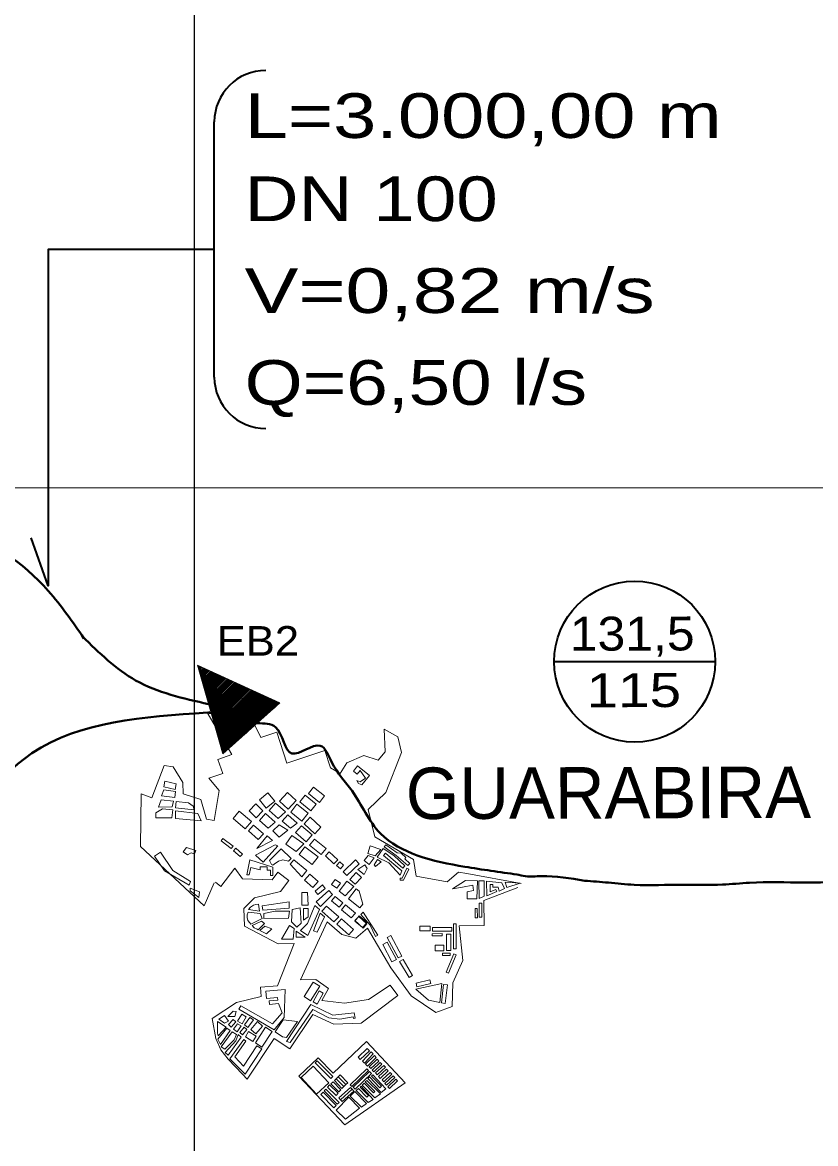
# Model space of a CAD drawing. Extents: x 0 to 1682, y 0 to 1188.
# Drawn here: x 1003.2 to 1062.2, y 569.6 to 652.9 of the extents above; entities that cross this region are included whole.
import ezdxf
from ezdxf.enums import TextEntityAlignment as Align

# ---------------------------------------------------------------- set-up
doc = ezdxf.new("R2010")
doc.units = 0
doc.header["$LTSCALE"] = 1.3
doc.linetypes.add('DOT_DASHED', pattern=[7.7, 5, -1.2, 0.3, -1.2])
doc.linetypes.add('LONG_DASHED', pattern=[7.5, 6, -1.5])
for name, color, linetype, lineweight in [('1', 7, 'DOT_DASHED', 13), ('4', 7, 'Continuous', 13), ('5', 7, 'LONG_DASHED', 25), ('6', 7, 'Continuous', 40), ('63', 7, 'Continuous', 25), ('8', 7, 'Continuous', 35), ('9', 7, 'Continuous', 40)]:
    doc.layers.add(name, color=color, linetype=linetype, lineweight=lineweight)

msp = doc.modelspace()

# ---------------------------------------------------------------- linework, layer by layer
at = {"layer": '1', "linetype": 'Continuous'}
for p, q in [((1026.861, 597.071), (1027.349, 597.865)), ((1016.751, 587.232), (1017.484, 588.935)), ((1019.152, 577.667), (1018.821, 577.878))]:
    msp.add_line(p, q, dxfattribs=at)
for points in [[(1026.861, 597.071), (1026.144, 597.484), (1025.726, 598.765), (1022.895, 597.841), (1022.145, 600.136), (1020.957, 599.748), (1019.155, 603.461), (1018.002, 602.901), (1018.321, 602.244), (1016.97, 601.589), (1018.815, 598.469), (1017.778, 598.113), (1018.135, 597.076), (1017.098, 596.719), (1017.874, 595.814), (1017.505, 593.579), (1016.935, 593.673), (1016.506, 595.124), (1015.18, 595.562), (1015.177, 596.402), (1014.445, 597.572), (1013.782, 597.659), (1012.862, 595.246), (1012.074, 595.547), (1012.011, 591.64), (1016.751, 587.232)], [(1040.301, 588.887), (1040.301, 588.887), (1036.266, 589.629), (1035.645, 589.744), (1034.799, 589.021), (1032.499, 589.43), (1032.307, 590.674), (1029.438, 592.363), (1028.942, 594.399), (1030.257, 595.647), (1031.416, 598.631), (1031.149, 599.8), (1030.13, 600.363), (1030.21, 598.665), (1029.685, 598.06), (1028.628, 598.397), (1027.349, 597.865)], [(1017.585, 588.981), (1017.983, 588.673), (1019.028, 590.023), (1019.594, 589.23), (1021.802, 589.17), (1022.22, 589.724), (1023.039, 589.107), (1022.421, 588.289), (1020.481, 587.818), (1019.688, 587.042), (1019.737, 585.715), (1022.258, 584.418), (1023.429, 584.444), (1022.201, 581.279), (1020.943, 581.186), (1020.993, 580.503), (1019.154, 580.044), (1017.35, 578.862), (1017.613, 577.369), (1017.987, 576.531), (1018.532, 575.853), (1019.591, 574.726), (1019.948, 574.346), (1021.955, 577.379), (1023.127, 576.604), (1024.815, 579.156), (1026.387, 578.433), (1028.411, 578.528), (1031.146, 580.574), (1030.575, 581.337), (1028.966, 580.278), (1027.187, 579.994), (1025.495, 580.2), (1025.993, 581.082), (1025.046, 581.758), (1023.911, 581.744), (1025.901, 586.038), (1026.972, 585.116), (1028.029, 584.83), (1028.884, 585.568), (1030.617, 582.633), (1032.136, 580.554), (1033.962, 579.298), (1035.191, 579.749), (1035.227, 581.513), (1035.963, 583.166), (1035.704, 585.754), (1037.563, 585.774), (1037.544, 587.633), (1040.071, 588.608)], [(1018.821, 577.878), (1018.017, 576.763), (1018.277, 576.575), (1018.981, 577.269), (1019.152, 577.667)]]:
    msp.add_lwpolyline(points, dxfattribs=at)
for points in [[(1029.039, 596.904), (1028.157, 597.622), (1027.843, 597.237), (1028.116, 597.015), (1028.338, 597.288), (1028.733, 596.729), (1028.343, 596.453), (1028.106, 596.54), (1028.214, 596.314), (1028.468, 596.221)], [(1014.608, 595.881), (1013.745, 596.079), (1013.837, 596.483), (1014.681, 596.29)], [(1013.572, 595.403), (1013.745, 595.854), (1014.633, 595.731), (1014.57, 595.274)], [(1021.37, 594.483), (1020.852, 595.105), (1021.474, 595.623), (1021.993, 595.001)], [(1022.997, 594.411), (1022.357, 595.003), (1022.948, 595.643), (1023.588, 595.051)], [(1025.321, 594.92), (1024.498, 595.587), (1024.882, 596.061), (1025.705, 595.394)], [(1014.386, 594.579), (1013.349, 594.576), (1013.547, 595.115), (1014.485, 595.017)], [(1016.012, 594.359), (1014.612, 594.517), (1014.665, 594.986), (1015.593, 594.88), (1015.924, 594.646)], [(1020.612, 593.78), (1020.094, 594.281), (1020.595, 594.799), (1021.113, 594.299)], [(1022.254, 593.724), (1021.584, 594.316), (1022.058, 594.854), (1022.792, 594.206)], [(1024.018, 593.532), (1023.18, 594.199), (1023.641, 594.779), (1024.479, 594.112)], [(1024.669, 594.295), (1023.862, 594.962), (1024.259, 595.443), (1025.067, 594.776)], [(1014.339, 593.766), (1013.164, 593.762), (1013.163, 594.137), (1013.662, 594.452), (1014.425, 594.366)], [(1014.614, 593.716), (1016.539, 593.559), (1016.275, 594.097), (1014.625, 594.279)], [(1019.809, 592.956), (1018.895, 593.73), (1019.353, 594.271), (1020.267, 593.498)], [(1021.511, 593.007), (1020.856, 593.583), (1021.308, 594.097), (1022.038, 593.455)], [(1023.168, 592.997), (1022.559, 593.527), (1022.959, 593.987), (1023.674, 593.365)], [(1020.769, 592.153), (1020.038, 592.805), (1020.423, 593.237), (1021.155, 592.585)], [(1022.319, 592.325), (1021.862, 592.795), (1022.332, 593.252), (1022.971, 592.844)], [(1024.326, 591.996), (1023.534, 592.678), (1023.974, 593.189), (1024.766, 592.507)], [(1024.963, 592.591), (1024.17, 593.319), (1024.623, 593.812), (1025.416, 593.084)], [(1018.895, 591.677), (1018.143, 592.238), (1018.013, 592.063), (1018.765, 591.502)], [(1021.833, 592.095), (1021.437, 592.429), (1020.658, 591.503)], [(1023.599, 591.278), (1022.822, 591.824), (1023.273, 592.466), (1024.166, 591.838)], [(1025.454, 591.041), (1024.586, 591.753), (1024.948, 592.194), (1025.816, 591.482)], [(1015.522, 591.016), (1015.196, 591.253), (1015.433, 591.579), (1016.121, 591.343), (1016.035, 591.092), (1015.784, 591.178)], [(1019.597, 591.078), (1019.095, 591.515), (1018.935, 591.33), (1019.436, 590.894)], [(1022.215, 591.685), (1021.139, 590.48), (1020.556, 591), (1022.017, 591.761)], [(1021.61, 590.603), (1022.474, 591.473), (1023.206, 590.746), (1023.008, 590.546), (1022.598, 590.652), (1022.279, 590.544), (1021.964, 590.339), (1021.843, 590.26), (1021.749, 590.293)], [(1024.787, 590.308), (1023.812, 591.051), (1024.239, 591.611), (1025.214, 590.868)], [(1029.462, 590.946), (1028.905, 591.126), (1029.085, 591.683), (1029.881, 591.425)], [(1031.654, 590.214), (1030.835, 590.973), (1030.05, 591.505), (1029.605, 590.848), (1030.473, 590.438), (1031.305, 589.509), (1031.44, 589.827), (1030.086, 590.982), (1030.217, 591.136), (1031.519, 590.025)], [(1031.881, 590.226), (1031.028, 590.985), (1030.129, 591.607), (1030.244, 591.773), (1031.103, 591.178), (1031.391, 591.145), (1031.732, 590.817), (1031.653, 590.734), (1032.022, 590.379)], [(1015.629, 588.777), (1013.801, 589.835), (1013.072, 590.934), (1013.512, 591.225), (1014.423, 589.851), (1015.74, 589.04)], [(1019.926, 589.533), (1020.135, 590.66), (1021.854, 590.117), (1021.856, 589.478), (1021.674, 589.477), (1021.673, 589.888), (1021.43, 589.887), (1021.429, 590.131), (1020.912, 590.129), (1020.913, 589.901), (1020.228, 590.082), (1020.087, 589.548)], [(1024.378, 589.85), (1023.403, 590.654), (1023.133, 590.326), (1024, 589.378)], [(1026.398, 590.359), (1025.758, 590.95), (1026.032, 591.246), (1026.672, 590.654)], [(1027.343, 589.479), (1027.069, 589.767), (1027.989, 590.643), (1028.263, 590.354)], [(1029.021, 590.297), (1028.645, 590.591), (1028.94, 590.967), (1029.394, 590.798)], [(1029.894, 590.504), (1029.487, 590.162), (1029.381, 590.288), (1029.633, 590.685)], [(1026.871, 589.98), (1026.596, 590.222), (1026.839, 590.497), (1027.113, 590.254)], [(1027.968, 588.842), (1027.587, 589.19), (1028.052, 589.698), (1028.439, 589.343)], [(1028.65, 589.559), (1028.178, 589.923), (1028.679, 590.274), (1028.86, 590.016)], [(1031.567, 589.134), (1031.306, 589.134), (1031.305, 589.281), (1031.453, 589.282), (1031.814, 590.021), (1031.965, 589.948)], [(1024.823, 588.604), (1024.213, 589.15), (1024.604, 589.586), (1025.214, 589.04)], [(1026.601, 588.548), (1026.221, 588.821), (1026.493, 589.202), (1026.874, 588.929)], [(1027.226, 587.987), (1026.784, 588.321), (1027.348, 589.067), (1027.867, 588.675)], [(1037.023, 587.756), (1036.288, 587.754), (1036.286, 588.285), (1036.773, 588.372), (1036.703, 588.763), (1035.957, 588.63), (1035.212, 588.497), (1036.172, 589.123), (1037.07, 589.083)], [(1037.177, 587.79), (1037.552, 587.951), (1037.548, 589.087), (1037.155, 589.086)], [(1038.67, 588.329), (1039.075, 588.528), (1038.877, 588.933), (1037.737, 589.062), (1037.753, 587.972), (1038.499, 588.29), (1038.434, 588.444), (1038.011, 588.264), (1038, 588.826), (1038.209, 588.83), (1038.213, 588.621), (1038.603, 588.629)], [(1039.246, 588.594), (1039.113, 589), (1040.241, 588.912)], [(1016.344, 587.865), (1015.718, 588.339), (1015.717, 588.552), (1016.393, 588.266)], [(1024.491, 587.29), (1024.013, 587.289), (1024.01, 588.224), (1024.433, 588.225)], [(1025.204, 588.073), (1024.991, 588.331), (1025.539, 588.784), (1025.752, 588.526)], [(1025.405, 587.175), (1025.084, 587.524), (1026.006, 588.37), (1026.279, 588.072)], [(1028.323, 587.093), (1027.47, 587.76), (1028.042, 588.491), (1028.266, 588.315), (1028.55, 587.367)], [(1020.87, 586.83), (1020.057, 586.964), (1020.202, 587.123), (1020.415, 587.274), (1020.599, 587.321), (1020.783, 587.369)], [(1023.079, 587.063), (1023.078, 587.52), (1021.055, 587.224), (1021.101, 586.91)], [(1025.327, 586.959), (1024.981, 587.27), (1024.44, 585.932), (1023.907, 585.396), (1024.465, 585.03)], [(1026.396, 586.037), (1025.497, 586.826), (1025.841, 587.219), (1026.764, 586.41)], [(1026.788, 587.134), (1026.224, 587.604), (1026.486, 587.918), (1027.05, 587.448)], [(1027.687, 586.33), (1026.956, 586.937), (1027.262, 587.305), (1027.993, 586.699)], [(1037.378, 586.397), (1037.375, 587.42), (1037.191, 587.42), (1037.194, 586.396)], [(1021.064, 586.282), (1020.905, 586.667), (1020.023, 586.763), (1019.938, 586.557), (1019.935, 586.36), (1019.995, 586.151), (1020.15, 585.967), (1020.225, 585.878)], [(1023.015, 586.306), (1021.191, 586.301), (1021.19, 586.668), (1022.035, 586.838), (1023.102, 586.841)], [(1023.629, 585.64), (1023.249, 586.04), (1023.28, 586.964), (1023.88, 587.088), (1023.961, 585.941)], [(1024.128, 586.165), (1024.125, 587.033), (1024.481, 587.034), (1024.483, 586.422)], [(1025.684, 586.414), (1025.361, 586.692), (1024.864, 585.387), (1025.145, 585.28)], [(1028.556, 585.572), (1027.946, 586.133), (1028.234, 586.446), (1028.844, 585.885)], [(1028.513, 585.625), (1027.955, 586.101), (1028.279, 586.481), (1028.855, 585.989)], [(1028.385, 586.591), (1028.566, 586.773), (1029.661, 585.061), (1029.486, 584.949), (1029.08, 585.798)], [(1037.05, 586.33), (1037.048, 587.026), (1036.878, 587.025), (1036.88, 586.33)], [(1021.005, 586.102), (1020.309, 585.783), (1020.472, 585.595), (1020.681, 585.498), (1020.772, 585.455), (1021.228, 585.91)], [(1021.395, 585.143), (1020.882, 585.398), (1021.248, 585.733), (1021.783, 585.534)], [(1023.376, 584.748), (1022.497, 584.746), (1023.094, 585.761), (1023.443, 585.555)], [(1026.609, 585.87), (1027.493, 585.082), (1027.849, 585.48), (1026.965, 586.269)], [(1032.78, 585.373), (1033.54, 585.375), (1033.539, 585.716), (1032.779, 585.714)], [(1033.724, 585.349), (1033.723, 585.625), (1035.152, 585.629), (1035.152, 585.353)], [(1035.471, 584.042), (1035.465, 585.905), (1035.269, 585.905), (1035.274, 584.041)], [(1024.254, 584.896), (1023.598, 584.894), (1023.596, 585.35)], [(1031.174, 583.36), (1030.343, 584.893), (1030.61, 585.038), (1031.441, 583.505)], [(1033.685, 585.165), (1034.445, 585.168), (1034.446, 584.997), (1033.685, 584.995)], [(1035.078, 583.91), (1035.074, 585.13), (1034.747, 585.129), (1034.75, 583.909)], [(1030.689, 583.07), (1030.017, 584.367), (1030.36, 584.545), (1031.033, 583.248)], [(1033.912, 583.893), (1034.567, 583.895), (1034.566, 584.302), (1033.91, 584.3)], [(1031.977, 581.906), (1031.266, 583.098), (1031.527, 583.253), (1032.238, 582.061)], [(1035.039, 583.726), (1034.463, 583.724), (1034.463, 583.54), (1035.04, 583.542)], [(1034.9, 582.243), (1035.472, 583.596), (1035.311, 583.664), (1034.738, 582.311)], [(1024.664, 580.188), (1025.336, 581.263), (1024.855, 581.564), (1024.183, 580.488)], [(1034.264, 580.062), (1033.424, 580.217), (1032.491, 581.041), (1034.404, 581.454)], [(1032.556, 581.225), (1033.591, 581.464), (1033.529, 581.733), (1032.494, 581.494)], [(1034.382, 580.023), (1034.548, 581.402), (1034.832, 581.367), (1034.666, 579.989)], [(1021.823, 578.457), (1019.477, 579.815), (1019.323, 579.55), (1021.965, 578.021), (1022.696, 578.936), (1022.782, 581.017), (1021.326, 580.893), (1021.372, 580.359), (1022.212, 580.43), (1022.229, 580.223), (1021.586, 580.168), (1021.608, 579.914), (1022.281, 579.971), (1022.536, 579.281)], [(1025.141, 579.938), (1025.602, 580.734), (1025.303, 580.907), (1024.843, 580.11)], [(1023.138, 577.069), (1024.825, 579.539), (1026.018, 578.92), (1026.831, 578.816), (1027.824, 578.998), (1027.847, 578.874), (1027.971, 578.897), (1027.902, 579.273), (1026.306, 579.116), (1024.674, 579.905), (1022.874, 577.162)], [(1018.263, 578.513), (1017.838, 578.803), (1018.274, 579.096), (1018.567, 578.66)], [(1019.042, 579.018), (1018.517, 579.017), (1018.895, 579.415), (1019.134, 579.39)], [(1019.573, 578.477), (1019.876, 578.994), (1019.542, 579.19), (1019.239, 578.672)], [(1019.998, 578.2), (1019.746, 578.384), (1020.156, 578.944), (1020.408, 578.76)], [(1017.749, 577.782), (1017.746, 578.63), (1018.383, 578.221), (1017.789, 577.57)], [(1018.688, 577.984), (1018.436, 578.142), (1017.763, 577.332), (1017.963, 576.922)], [(1018.753, 578.222), (1018.554, 578.407), (1018.918, 578.799), (1019.117, 578.614)], [(1019.229, 578.476), (1018.939, 578.064), (1019.202, 577.879), (1019.513, 578.319)], [(1019.602, 577.642), (1019.39, 577.814), (1019.719, 578.221), (1019.931, 578.049)], [(1020.21, 578.055), (1020.581, 577.724), (1021.093, 578.3), (1020.722, 578.631)], [(1020.557, 577.062), (1021.048, 576.745), (1021.796, 577.905), (1021.305, 578.222)], [(1022.581, 577.505), (1022.037, 577.861), (1022.623, 578.755), (1023.689, 578.635), (1022.872, 577.44)], [(1019.51, 577.469), (1019.271, 577.667), (1019.101, 577.203), (1018.309, 576.326), (1018.523, 576.134)], [(1019.809, 574.727), (1021.035, 576.599), (1020.663, 576.843), (1019.672, 575.33), (1019.025, 576.024), (1019.855, 577.192), (1019.687, 577.312), (1018.659, 575.866)], [(1019.814, 577.497), (1020.371, 577.154), (1020.615, 577.55), (1020.058, 577.892)], [(1027.201, 570.968), (1023.784, 574.584), (1025.233, 575.952), (1026.328, 574.793), (1028.814, 577.144), (1031.695, 574.095)], [(1028.192, 575.992), (1028.866, 576.627), (1029.026, 576.457), (1028.352, 575.822)], [(1028.509, 575.691), (1029.154, 576.384), (1029.31, 576.239), (1028.665, 575.546)], [(1026.173, 574.417), (1025.009, 575.566), (1025.157, 575.715), (1026.32, 574.567)], [(1028.74, 575.462), (1029.399, 576.111), (1029.542, 575.966), (1028.883, 575.317)], [(1029.014, 575.275), (1029.616, 575.838), (1029.741, 575.704), (1029.139, 575.141)], [(1029.233, 575.032), (1029.834, 575.595), (1029.96, 575.461), (1029.358, 574.898)], [(1025.106, 573.244), (1023.951, 574.474), (1024.848, 575.316), (1026.003, 574.086)], [(1028.968, 574.993), (1027.721, 573.81), (1027.593, 573.945), (1028.839, 575.128)], [(1027.965, 573.621), (1029.175, 574.768), (1029.031, 574.921), (1027.82, 573.774)], [(1029.492, 574.817), (1030.094, 575.38), (1030.219, 575.245), (1029.617, 574.683)], [(1029.708, 574.544), (1030.31, 575.107), (1030.436, 574.973), (1029.834, 574.41)], [(1029.968, 574.3), (1030.57, 574.863), (1030.695, 574.729), (1030.093, 574.166)], [(1026.563, 573.149), (1025.923, 573.768), (1026.077, 573.928), (1026.717, 573.309)], [(1026.76, 573.42), (1026.174, 574.003), (1026.326, 574.157), (1026.913, 573.573)], [(1026.993, 573.673), (1026.425, 574.256), (1026.567, 574.394), (1027.135, 573.811)], [(1027.135, 573.811), (1026.567, 574.394), (1026.708, 574.532), (1027.277, 573.949)], [(1027.277, 573.949), (1026.708, 574.532), (1026.85, 574.67), (1027.418, 574.087)], [(1029.854, 573.267), (1029.423, 572.96), (1028.485, 573.92), (1028.631, 574.062), (1029.34, 573.336), (1029.437, 573.431), (1028.724, 574.16), (1028.828, 574.262)], [(1030.249, 573.646), (1029.908, 573.357), (1028.906, 574.398), (1029.035, 574.522), (1029.804, 573.723), (1029.918, 573.832), (1029.193, 574.586), (1029.296, 574.685)], [(1030.184, 574.042), (1030.786, 574.605), (1030.911, 574.471), (1030.309, 573.908)], [(1030.4, 573.798), (1031.002, 574.361), (1031.128, 574.227), (1030.526, 573.664)], [(1026.395, 572.239), (1025.43, 573.227), (1025.595, 573.388), (1026.56, 572.4)], [(1026.646, 572.492), (1025.672, 573.48), (1025.804, 573.609), (1026.778, 572.622)], [(1026.874, 572.828), (1027.744, 573.605), (1027.621, 573.742), (1026.751, 572.965)], [(1026.996, 572.691), (1027.866, 573.468), (1027.744, 573.605), (1026.874, 572.828)], [(1028.822, 572.553), (1028.436, 572.272), (1027.597, 573.098), (1027.937, 573.443)], [(1029.298, 572.842), (1028.93, 572.625), (1028.055, 573.514), (1028.209, 573.666), (1028.837, 573.028), (1028.952, 573.142), (1028.339, 573.764), (1028.415, 573.838)], [(1028.302, 572.191), (1027.243, 571.378), (1026.557, 572.042), (1027.496, 573.01)]]:
    msp.add_lwpolyline(points, close=True, dxfattribs=at)
at = {"layer": '4'}
for p, q in [((1016.276, 605.069), (1016.304, 605.098)), ((1016.301, 604.981), (1016.382, 605.062)), ((1016.326, 604.893), (1016.459, 605.026)), ((1016.351, 604.804), (1016.537, 604.991)), ((1016.376, 604.716), (1016.614, 604.955)), ((1016.401, 604.628), (1016.692, 604.92)), ((1016.426, 604.54), (1016.77, 604.884)), ((1016.451, 604.452), (1016.847, 604.848)), ((1016.476, 604.364), (1016.925, 604.813)), ((1016.501, 604.276), (1017.002, 604.777)), ((1016.526, 604.187), (1017.08, 604.742)), ((1016.551, 604.099), (1017.157, 604.706)), ((1016.576, 604.011), (1017.235, 604.67)), ((1016.601, 603.923), (1017.312, 604.635)), ((1016.625, 603.835), (1017.39, 604.599)), ((1016.65, 603.747), (1017.467, 604.564)), ((1016.675, 603.659), (1017.545, 604.528)), ((1016.7, 603.57), (1017.622, 604.492)), ((1016.725, 603.482), (1017.7, 604.457)), ((1016.75, 603.394), (1017.778, 604.421)), ((1016.775, 603.306), (1017.855, 604.386)), ((1016.8, 603.218), (1017.933, 604.35)), ((1016.825, 603.13), (1018.01, 604.314)), ((1016.85, 603.041), (1018.088, 604.279)), ((1016.875, 602.953), (1018.165, 604.243)), ((1016.9, 602.865), (1018.243, 604.208)), ((1016.925, 602.777), (1018.32, 604.172)), ((1016.95, 602.689), (1018.398, 604.136)), ((1016.975, 602.601), (1018.475, 604.101)), ((1017, 602.513), (1018.553, 604.065)), ((1017.025, 602.424), (1018.63, 604.03)), ((1017.05, 602.336), (1018.708, 603.994)), ((1017.075, 602.248), (1018.786, 603.958)), ((1017.1, 602.16), (1018.863, 603.923)), ((1017.125, 602.072), (1018.941, 603.887)), ((1017.15, 601.984), (1019.018, 603.852)), ((1017.175, 601.896), (1019.096, 603.816)), ((1017.2, 601.807), (1019.173, 603.78)), ((1017.225, 601.719), (1019.251, 603.745)), ((1017.25, 601.631), (1019.328, 603.709)), ((1017.275, 601.543), (1019.406, 603.674)), ((1017.3, 601.455), (1019.483, 603.638)), ((1017.325, 601.367), (1019.561, 603.602)), ((1017.35, 601.278), (1019.638, 603.567)), ((1017.375, 601.19), (1019.716, 603.531)), ((1017.4, 601.102), (1019.794, 603.496)), ((1017.425, 601.014), (1019.871, 603.46)), ((1017.45, 600.926), (1019.949, 603.424)), ((1017.475, 600.838), (1020.026, 603.389)), ((1017.5, 600.75), (1020.104, 603.353)), ((1017.525, 600.661), (1020.181, 603.318)), ((1017.55, 600.573), (1020.259, 603.282)), ((1017.575, 600.485), (1020.336, 603.246)), ((1017.6, 600.397), (1020.414, 603.211)), ((1017.625, 600.309), (1020.491, 603.175)), ((1017.65, 600.221), (1020.569, 603.14)), ((1017.675, 600.133), (1020.646, 603.104)), ((1017.7, 600.044), (1020.724, 603.068)), ((1017.725, 599.956), (1020.802, 603.033)), ((1017.75, 599.868), (1020.879, 602.997)), ((1017.775, 599.78), (1020.957, 602.962)), ((1017.8, 599.692), (1021.034, 602.926)), ((1017.825, 599.604), (1021.112, 602.89)), ((1017.85, 599.515), (1021.189, 602.855)), ((1017.875, 599.427), (1021.267, 602.819)), ((1017.9, 599.339), (1021.344, 602.784)), ((1017.925, 599.251), (1021.422, 602.748)), ((1017.95, 599.163), (1021.499, 602.712)), ((1017.975, 599.075), (1021.577, 602.677)), ((1018, 598.987), (1021.654, 602.641)), ((1018.025, 598.898), (1021.732, 602.606)), ((1018.05, 598.81), (1021.81, 602.57)), ((1018.075, 598.722), (1021.887, 602.534)), ((1018.1, 598.634), (1021.965, 602.499)), ((1018.125, 598.546), (1022.042, 602.463)), ((1018.803, 599.111), (1022.12, 602.428)), ((1019.849, 600.044), (1022.197, 602.392)), ((1020.896, 600.977), (1022.275, 602.356)), ((1021.942, 601.91), (1022.352, 602.321))]:
    msp.add_line(p, q, dxfattribs=at)
msp.add_lwpolyline([(1018.134, 598.514), (1016.262, 605.117), (1022.385, 602.306)], close=True, dxfattribs=at)
at = {"layer": '6'}
msp.add_line((1017.276, 601.541), (1016.97, 601.589), dxfattribs=at)
for points in [[(1007.819, 607.104), (1005.163, 610.631), (998.165, 615.452), (991.956, 617.614), (988.339, 620.2)], [(1017.083, 602.22), (1011.661, 603.981), (1007.712, 607.245)], [(1016.97, 601.589), (1003.954, 598.568), (997.364, 589.92), (994.779, 579.078), (994.779, 565.267), (988.706, 558.168), (983.925, 548.616), (978.11, 542.421)], [(1040.015, 589.559), (1036.116, 590.139), (1032.589, 590.981), (1029.853, 592.61), (1027.748, 595.765), (1026.221, 597.92), (1025.379, 599.129), (1023.274, 598.551), (1022.064, 600.496), (1020.692, 600.795)], [(1045.029, 589.096), (1041.798, 589.437), (1040.625, 589.434), (1039.98, 589.564)], [(1126.716, 579.526), (1124.889, 580.049), (1123.647, 580.271), (1122.606, 580.519), (1121.797, 580.75), (1121.042, 580.994), (1120.266, 581.327), (1119.486, 581.689), (1118.583, 582.275), (1117.64, 582.744), (1116.765, 583.134), (1115.689, 583.21), (1114.922, 583.207), (1114.416, 583.402), (1113.554, 583.198), (1112.303, 583.02), (1111.535, 582.909), (1110.519, 582.906), (1108.421, 582.9), (1106.499, 582.894), (1105.969, 582.979), (1105.084, 583.089), (1104.378, 583.325), (1103.629, 583.613), (1103.194, 583.832), (1102.689, 584.132), (1102.274, 584.477), (1101.552, 584.897), (1100.458, 584.894), (1099.896, 584.635), (1099.029, 584.442), (1098.211, 584.252), (1097.64, 584.081), (1097.112, 583.98), (1096.547, 583.811), (1096.097, 583.64), (1095.748, 583.52), (1095.355, 583.449), (1094.328, 583.446), (1093.674, 583.215), (1093.144, 583.033), (1092.527, 582.894), (1091.835, 582.892), (1091.193, 582.788), (1090.598, 582.786), (1090.159, 582.785), (1089.353, 582.782), (1088.725, 582.523), (1088.267, 582.34), (1087.656, 582.338), (1087.056, 582.414), (1086.54, 582.687), (1085.682, 583.222), (1084.562, 583.862), (1083.633, 584.413), (1082.414, 585.019), (1081.257, 585.54), (1080.245, 585.916), (1079.133, 586.215), (1078.02, 586.405), (1077.185, 586.651), (1076.355, 586.833), (1075.384, 587.055), (1074.589, 587.233), (1073.691, 587.428), (1072.627, 587.618), (1072.225, 587.617), (1071.937, 587.719), (1071.372, 587.951), (1070.463, 588.082), (1069.404, 588.208), (1068.417, 588.354), (1067.766, 588.466), (1067.066, 588.632), (1066.356, 588.899), (1065.485, 588.896), (1063.966, 588.972), (1062.086, 588.967), (1061.337, 588.965), (1057.275, 588.952), (1055.259, 588.814), (1052.322, 588.805), (1048.698, 588.794), (1046.791, 588.956), (1045.01, 589.096)]]:
    msp.add_spline(points, degree=3, dxfattribs=at)
at = {"layer": '63'}
msp.add_line((1016.026, 427.142), (1016.026, 783.93), dxfattribs=at)
at = {"layer": '63', "lineweight": 13}
msp.add_line((1640.404, 618.279), (952.314, 618.279), dxfattribs=at)
at = {"layer": '8'}
msp.add_line((1017.506, 626.515), (1017.506, 645.471), dxfattribs=at)
msp.add_lwpolyline([(1017.506, 635.993), (1005.156, 635.993), (1005.156, 611.002), (1003.89, 614.569)], dxfattribs=at)
for centre, start, end in [((1021.328, 645.471), 90, 180), ((1021.328, 645.471), 90, 180), ((1021.328, 645.471), 90, 180), ((1021.328, 626.515), 180, 270)]:
    msp.add_arc(centre, 3.823, start, end, dxfattribs=at)
at = {"layer": '9', "lineweight": 35}
msp.add_line((1042.76, 605.377), (1054.731, 605.377), dxfattribs=at)
msp.add_circle((1048.746, 605.377), 5.985, dxfattribs=at)

# ---------------------------------------------------------------- texts
at = {"layer": '5', "width": 1.1}
msp.add_text('EB2', height=2.2, rotation=0.006, dxfattribs=at).set_placement((1020.743, 605.815), align=Align.CENTER)
at = {"layer": '8'}
for s, width, p in [('L=3.000,00 m', 1.3, (1019.758, 644.28)), ('DN 100', 1.25, (1019.758, 638.1)), ('V=0,82 m/s', 1.35, (1019.758, 631.276)), ('Q=6,50 l/s', 1.25, (1019.758, 624.453))]:
    msp.add_text(s, height=3.319, dxfattribs=dict(at, width=width)).set_placement(p)
at = {"layer": '9'}
for s, width, p in [('131,5', 1.1, (1048.561, 606.196)), ('115', 1.25, (1048.682, 601.994))]:
    msp.add_text(s, height=2.52, rotation=0.17, dxfattribs=dict(at, width=width)).set_placement(p, align=Align.CENTER)
msp.add_text('GUARABIRA', height=3.823, rotation=0.17, dxfattribs=at).set_placement((1031.739, 593.677))

doc.saveas('drawing.dxf')
